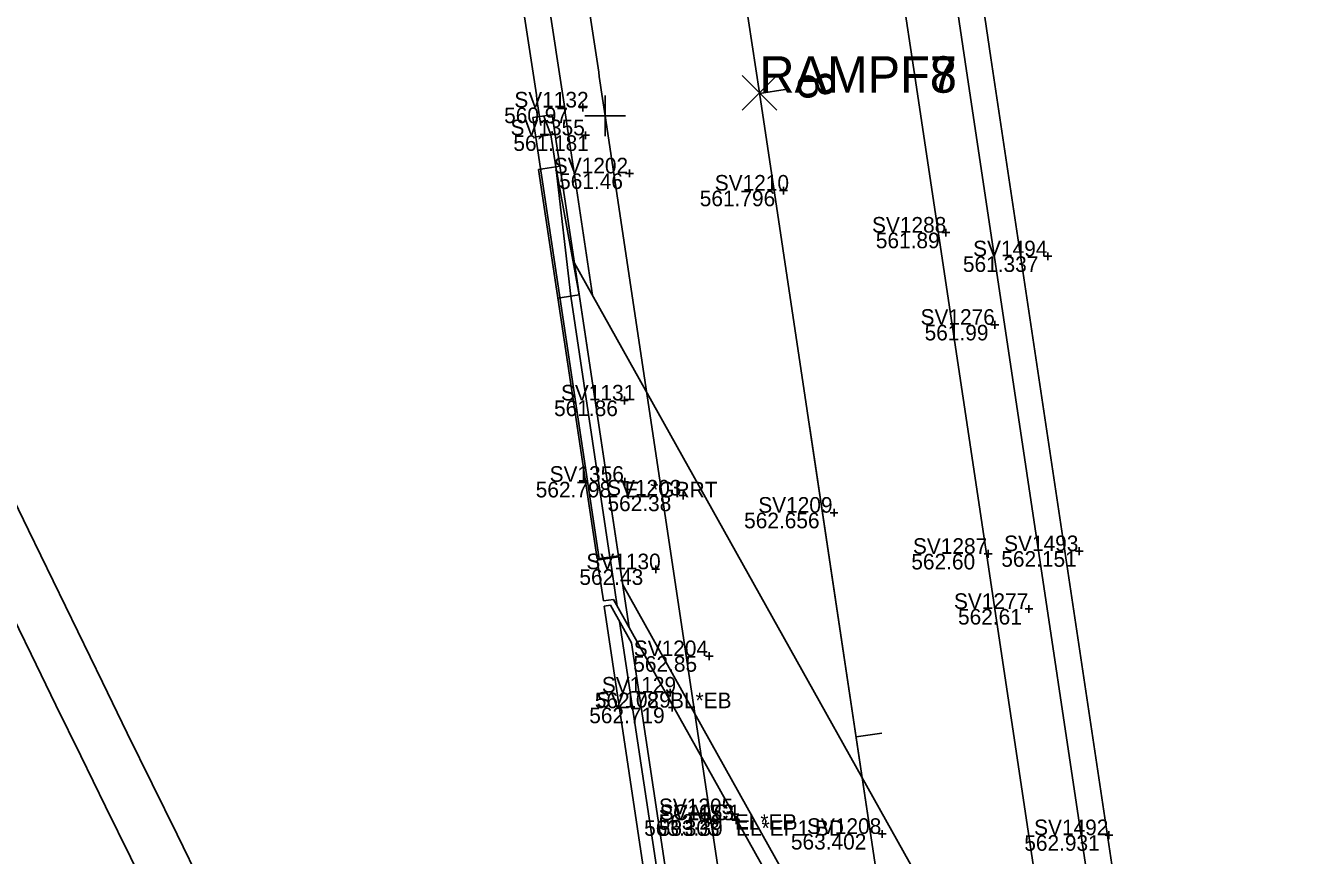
# Model space of a CAD drawing. Extents: x 6334 to 41599, y 9030 to 59113.
# Drawn here: x 21027.9 to 21126.9, y 34551.9 to 34615.6 of the extents above; entities that cross this region are included whole.
import ezdxf

# ---------------------------------------------------------------- set-up
doc = ezdxf.new("R2010")
doc.units = 0
for name, color, linetype in [('BR_P_Rail_Object', 7, 'Continuous'), ('BR_P_Sub_Backwall', 7, 'Continuous'), ('BR_X_Gen_Approach_Slab', 7, 'Continuous'), ('BR_X_Slab_Centerline', 7, 'Continuous'), ('BR_X_SV_Deck_Top', 7, 'Continuous'), ('BR_X_SV_Deck_Top_Text', 7, 'Continuous'), ('GE_P_CL_20', 7, 'Continuous'), ('GE_X_CL_20', 7, 'Continuous'), ('GE_X_CL_50', 7, 'Continuous'), ('GK_Visualization', 7, 'Continuous'), ('PM_X_CL_Double_Solid', 7, 'Continuous'), ('PM_X_Lane_Line', 7, 'Continuous'), ('PV_X_EOP', 7, 'Continuous'), ('PV_X_Shoulder', 7, 'Continuous'), ('RD_X_GR_Lt', 7, 'Continuous'), ('RD_X_GR_Rt', 7, 'Continuous'), ('SV_X_Shot_Marker', 7, 'Continuous'), ('SV_X_Text_Comment', 7, 'Continuous'), ('SV_X_Text_Elevation', 7, 'Continuous'), ('SV_X_Text_Name', 7, 'Continuous')]:
    doc.layers.add(name, color=color, linetype=linetype)

msp = doc.modelspace()

# ---------------------------------------------------------------- linework, layer by layer
at = {"layer": 'BR_P_Rail_Object'}
msp.add_line((21073.051, 34571.516), (21074.266, 34569.344), dxfattribs=at)
at = {"layer": 'BR_P_Sub_Backwall'}
msp.add_line((21118.505, 34490.24), (21073.051, 34571.516), dxfattribs=at)
at = {"layer": 'BR_X_Gen_Approach_Slab'}
for p, q in [((21070.057, 34597.364), (21073.77, 34572.641)), ((21114.297, 34518.26), (21070.057, 34597.364)), ((21118.01, 34493.537), (21073.77, 34572.641))]:
    msp.add_line(p, q, dxfattribs=at)
at = {"layer": 'BR_X_Slab_Centerline'}
msp.add_line((21088.117, 34584.844), (21156.74, 34127.951), dxfattribs=at)
at = {"layer": 'BR_X_SV_Deck_Top'}
for p, q in [((21068.346, 34608.759), (21066.862, 34608.536)), ((21068.346, 34608.759), (21066.862, 34608.536)), ((21071.953, 34574.645), (21066.862, 34608.536)), ((21068.239, 34607.226), (21067.686, 34608.66)), ((21073.436, 34574.868), (21068.346, 34608.759)), ((21068.568, 34607.276), (21067.085, 34607.053)), ((21068.61, 34604.754), (21068.239, 34607.226)), ((21068.94, 34604.803), (21067.292, 34604.556)), ((21071.788, 34574.621), (21067.292, 34604.556)), ((21069.766, 34594.815), (21068.61, 34604.754)), ((21070.425, 34594.914), (21068.61, 34604.754)), ((21070.425, 34594.914), (21068.777, 34594.667)), ((21072.777, 34574.769), (21069.766, 34594.815)), ((21071.788, 34574.621), (21073.436, 34574.868)), ((21071.8, 34574.538), (21073.448, 34574.786)), ((21072.272, 34571.399), (21071.8, 34574.538)), ((21073.344, 34570.992), (21072.789, 34574.687)), ((21074.266, 34569.344), (21073.448, 34574.786)), ((21073.051, 34571.516), (21072.272, 34571.399)), ((21072.828, 34571.061), (21072.333, 34570.987)), ((21072.333, 34570.987), (21124.136, 34226.081)), ((21074.441, 34568.177), (21072.828, 34571.061)), ((21073.519, 34569.825), (21125.209, 34225.674)), ((21074.441, 34568.177), (21126.13, 34224.026))]:
    msp.add_line(p, q, dxfattribs=at)
at = {"layer": 'BR_X_SV_Deck_Top_Text'}
for p, q in [((21077.875, 34563.2), (21077.275, 34563.2)), ((21077.575, 34563.5), (21077.575, 34562.9)), ((21082.476, 34554.849), (21082.476, 34554.249)), ((21082.776, 34554.549), (21082.176, 34554.549))]:
    msp.add_line(p, q, dxfattribs=at)
at = {"layer": 'GE_P_CL_20'}
for p, q in [((21084.28, 34610.389), (21086.258, 34610.687)), ((21091.707, 34560.944), (21093.684, 34561.241))]:
    msp.add_line(p, q, dxfattribs=at)
at = {"layer": 'GE_X_CL_20'}
msp.add_arc((24529.938, 36271.897), 3906.53, 186.216667, 209.216667, dxfattribs=at)
at = {"layer": 'GE_X_CL_50'}
msp.add_arc((32581.775, 39251.958), 12277.667, 194.525, 202.7166667, dxfattribs=at)
at = {"layer": 'GK_Visualization'}
for p, q in [((21051.298, 34829.989), (21084.271, 34610.451)), ((21051.298, 34829.989), (21084.271, 34610.451)), ((21082.938, 34609.116), (21085.604, 34611.786)), ((21082.938, 34611.786), (21085.604, 34609.116)), ((21082.938, 34609.116), (21085.604, 34611.786)), ((21082.938, 34611.786), (21085.604, 34609.116)), ((21072.416, 34610.24), (21072.416, 34607.12)), ((21084.271, 34610.451), (21262.514, 33423.702)), ((21084.271, 34610.451), (21262.514, 33423.702)), ((21073.976, 34608.68), (21070.856, 34608.68))]:
    msp.add_line(p, q, dxfattribs=at)
for centre, radius, start, end in [((32581.775, 39251.958), 12277.667, 194.525, 202.7166667), ((32581.775, 39251.958), 12277.667, 194.525, 202.7166667), ((24529.914, 36271.941), 3906.53, 186.214966, 209.213797), ((24529.914, 36271.941), 3906.53, 186.214966, 209.213797), ((24529.938, 36271.897), 3906.53, 186.216667, 209.216667), ((24529.938, 36271.897), 3906.53, 186.216667, 209.216667)]:
    msp.add_arc(centre, radius, start, end, dxfattribs=at)
msp.add_spline([(21035.844, 34805.209), (21036.519, 34802.592), (21037.187, 34799.973), (21037.847, 34797.352), (21038.5, 34794.729), (21039.146, 34792.105), (21039.786, 34789.479), (21040.418, 34786.852), (21041.044, 34784.222), (21041.663, 34781.591), (21042.276, 34778.959), (21042.882, 34776.325), (21043.482, 34773.69), (21044.075, 34771.053), (21044.663, 34768.415), (21045.244, 34765.776), (21045.819, 34763.135), (21046.389, 34760.493), (21046.953, 34757.85), (21047.511, 34755.205), (21048.063, 34752.56), (21048.61, 34749.913), (21049.152, 34747.265), (21049.688, 34744.616), (21050.22, 34741.966), (21050.746, 34739.315), (21051.267, 34736.663), (21051.783, 34734.01), (21052.295, 34731.356), (21052.802, 34728.702), (21053.304, 34726.046), (21053.802, 34723.389), (21054.295, 34720.732), (21054.785, 34718.074), (21055.27, 34715.415), (21055.751, 34712.756), (21056.228, 34710.095), (21056.701, 34707.435), (21057.17, 34704.773), (21057.636, 34702.111), (21058.098, 34699.448), (21058.557, 34696.784), (21059.012, 34694.12), (21059.464, 34691.456), (21059.913, 34688.79), (21060.359, 34686.125), (21060.802, 34683.459), (21061.242, 34680.792), (21061.679, 34678.125), (21062.114, 34675.457), (21062.546, 34672.789), (21062.976, 34670.121), (21063.403, 34667.452), (21063.828, 34664.783), (21064.251, 34662.114), (21064.672, 34659.444), (21065.091, 34656.774), (21065.508, 34654.104), (21065.923, 34651.433), (21066.337, 34648.762), (21066.749, 34646.091), (21067.16, 34643.42), (21067.569, 34640.748), (21067.977, 34638.077), (21068.384, 34635.405), (21068.79, 34632.733), (21069.196, 34630.061), (21069.6, 34627.388), (21070.003, 34624.716), (21070.406, 34622.043), (21070.809, 34619.371), (21071.211, 34616.698), (21071.613, 34614.026), (21072.014, 34611.353), (21072.416, 34608.68)], degree=3, dxfattribs=at)
at = {"layer": 'PM_X_CL_Double_Solid'}
for p, q in [((21061.445, 34762.427), (21084.271, 34610.451)), ((21084.271, 34610.451), (21262.514, 33423.702))]:
    msp.add_line(p, q, dxfattribs=at)
at = {"layer": 'PM_X_Lane_Line'}
for start in [186.216667, 191.336069]:
    msp.add_arc((24529.938, 36271.897), 3906.53, start, 209.216667, dxfattribs=at)
at = {"layer": 'PV_X_EOP'}
for p, q in [((21063.164, 34831.771), (21096.138, 34612.234)), ((21096.138, 34612.234), (21274.381, 33425.485)), ((21072.403, 34608.678), (21072.404, 34608.669)), ((21072.404, 34608.669), (21250.647, 33421.92))]:
    msp.add_line(p, q, dxfattribs=at)
for centre, radius, start, end in [((24529.938, 36271.897), 3918.53, 191.336069, 209.216667), ((24531.789, 36272.609), 3896.493, 192.870453, 209.21252)]:
    msp.add_arc(centre, radius, start, end, dxfattribs=at)
msp.add_spline([(21035.844, 34805.209), (21036.519, 34802.592), (21037.187, 34799.973), (21037.847, 34797.352), (21038.5, 34794.729), (21039.146, 34792.105), (21039.786, 34789.479), (21040.418, 34786.852), (21041.044, 34784.222), (21041.663, 34781.591), (21042.276, 34778.959), (21042.882, 34776.325), (21043.482, 34773.69), (21044.075, 34771.053), (21044.663, 34768.415), (21045.244, 34765.776), (21045.819, 34763.135), (21046.389, 34760.493), (21046.953, 34757.85), (21047.511, 34755.205), (21048.063, 34752.56), (21048.61, 34749.913), (21049.152, 34747.265), (21049.688, 34744.616), (21050.22, 34741.966), (21050.746, 34739.315), (21051.267, 34736.663), (21051.783, 34734.01), (21052.295, 34731.356), (21052.802, 34728.702), (21053.304, 34726.046), (21053.802, 34723.389), (21054.295, 34720.732), (21054.785, 34718.074), (21055.27, 34715.415), (21055.751, 34712.756), (21056.228, 34710.095), (21056.701, 34707.435), (21057.17, 34704.773), (21057.636, 34702.111), (21058.098, 34699.448), (21058.557, 34696.784), (21059.012, 34694.12), (21059.464, 34691.456), (21059.913, 34688.79), (21060.359, 34686.125), (21060.802, 34683.459), (21061.242, 34680.792), (21061.679, 34678.125), (21062.114, 34675.457), (21062.546, 34672.789), (21062.976, 34670.121), (21063.403, 34667.452), (21063.828, 34664.783), (21064.251, 34662.114), (21064.672, 34659.444), (21065.091, 34656.774), (21065.508, 34654.104), (21065.923, 34651.433), (21066.337, 34648.762), (21066.749, 34646.091), (21067.16, 34643.42), (21067.569, 34640.748), (21067.977, 34638.077), (21068.384, 34635.405), (21068.79, 34632.733), (21069.196, 34630.061), (21069.6, 34627.388), (21070.003, 34624.716), (21070.406, 34622.043), (21070.809, 34619.371), (21071.211, 34616.698), (21071.613, 34614.026), (21072.014, 34611.353), (21072.416, 34608.68)], degree=3, dxfattribs=at)
at = {"layer": 'PV_X_Shoulder'}
for p, q in [((21067.12, 34832.366), (21100.093, 34612.828)), ((21100.093, 34612.828), (21114.297, 34518.26)), ((21069.436, 34608.233), (21069.437, 34608.224)), ((21069.437, 34608.224), (21071.44, 34594.892))]:
    msp.add_line(p, q, dxfattribs=at)
for radius, start in [(3926.53, 191.341411), (3890.53, 192.866306)]:
    msp.add_arc((24529.938, 36271.897), radius, start, 209.216667, dxfattribs=at)
msp.add_spline([(21032.939, 34804.46), (21033.613, 34801.847), (21034.279, 34799.236), (21034.937, 34796.623), (21035.588, 34794.008), (21036.233, 34791.392), (21036.87, 34788.773), (21037.501, 34786.153), (21038.125, 34783.531), (21038.742, 34780.908), (21039.353, 34778.283), (21039.958, 34775.656), (21040.556, 34773.028), (21041.148, 34770.398), (21041.734, 34767.766), (21042.313, 34765.134), (21042.887, 34762.499), (21043.455, 34759.864), (21044.018, 34757.227), (21044.575, 34754.589), (21045.126, 34751.949), (21045.672, 34749.308), (21046.212, 34746.667), (21046.747, 34744.023), (21047.277, 34741.379), (21047.803, 34738.734), (21048.323, 34736.087), (21048.838, 34733.44), (21049.349, 34730.791), (21049.855, 34728.141), (21050.356, 34725.491), (21050.853, 34722.839), (21051.345, 34720.187), (21051.834, 34717.533), (21052.318, 34714.879), (21052.798, 34712.224), (21053.274, 34709.568), (21053.747, 34706.911), (21054.216, 34704.254), (21054.681, 34701.596), (21055.142, 34698.937), (21055.6, 34696.277), (21056.055, 34693.617), (21056.506, 34690.955), (21056.955, 34688.294), (21057.4, 34685.631), (21057.842, 34682.968), (21058.282, 34680.305), (21058.719, 34677.641), (21059.153, 34674.976), (21059.584, 34672.311), (21060.014, 34669.645), (21060.44, 34666.979), (21060.865, 34664.313), (21061.288, 34661.646), (21061.708, 34658.978), (21062.127, 34656.31), (21062.543, 34653.642), (21062.959, 34650.973), (21063.372, 34648.304), (21063.784, 34645.634), (21064.194, 34642.965), (21064.604, 34640.295), (21065.012, 34637.624), (21065.418, 34634.953), (21065.824, 34632.283), (21066.229, 34629.611), (21066.634, 34626.94), (21067.037, 34624.268), (21067.44, 34621.596), (21067.842, 34618.924), (21068.244, 34616.252), (21068.646, 34613.58), (21069.048, 34610.907), (21069.449, 34608.234)], degree=3, dxfattribs=at)
at = {"layer": 'RD_X_GR_Lt'}
for p, q in [((21058.92, 34900.43), (21102.071, 34613.125)), ((21102.071, 34613.125), (21117.462, 34510.655))]:
    msp.add_line(p, q, dxfattribs=at)
at = {"layer": 'RD_X_GR_Rt'}
msp.add_spline([(21031.002, 34803.96), (21031.676, 34801.35), (21032.34, 34798.744), (21032.997, 34796.137), (21033.647, 34793.527), (21034.29, 34790.916), (21034.926, 34788.303), (21035.556, 34785.688), (21036.178, 34783.071), (21036.795, 34780.452), (21037.405, 34777.832), (21038.008, 34775.21), (21038.605, 34772.586), (21039.196, 34769.961), (21039.781, 34767.334), (21040.36, 34764.706), (21040.933, 34762.076), (21041.5, 34759.445), (21042.061, 34756.812), (21042.617, 34754.178), (21043.168, 34751.542), (21043.713, 34748.906), (21044.252, 34746.268), (21044.787, 34743.628), (21045.316, 34740.988), (21045.84, 34738.346), (21046.36, 34735.703), (21046.875, 34733.059), (21047.384, 34730.414), (21047.89, 34727.768), (21048.39, 34725.121), (21048.887, 34722.472), (21049.379, 34719.823), (21049.867, 34717.173), (21050.35, 34714.522), (21050.83, 34711.87), (21051.306, 34709.217), (21051.777, 34706.563), (21052.246, 34703.908), (21052.71, 34701.252), (21053.171, 34698.596), (21053.629, 34695.939), (21054.083, 34693.281), (21054.534, 34690.622), (21054.982, 34687.963), (21055.427, 34685.303), (21055.869, 34682.642), (21056.308, 34679.98), (21056.745, 34677.318), (21057.179, 34674.656), (21057.61, 34671.992), (21058.039, 34669.328), (21058.465, 34666.664), (21058.89, 34663.999), (21059.312, 34661.333), (21059.732, 34658.667), (21060.151, 34656.001), (21060.567, 34653.334), (21060.982, 34650.666), (21061.395, 34647.998), (21061.807, 34645.33), (21062.218, 34642.661), (21062.627, 34639.992), (21063.034, 34637.323), (21063.441, 34634.653), (21063.847, 34631.982), (21064.252, 34629.312), (21064.656, 34626.641), (21065.059, 34623.97), (21065.462, 34621.298), (21065.865, 34618.627), (21066.267, 34615.955), (21066.668, 34613.282), (21067.07, 34610.61), (21067.471, 34607.937)], degree=3, dxfattribs=at)
at = {"layer": 'SV_X_Shot_Marker'}
for p, q in [((21071.001, 34609.315), (21070.401, 34609.315)), ((21070.701, 34609.615), (21070.701, 34609.015)), ((21071.199, 34607.179), (21070.599, 34607.179)), ((21070.899, 34607.479), (21070.899, 34606.879)), ((21074.585, 34604.252), (21073.985, 34604.252)), ((21074.285, 34604.552), (21074.285, 34603.952)), ((21086.129, 34603.229), (21086.129, 34602.629)), ((21086.429, 34602.929), (21085.829, 34602.929)), ((21098.907, 34599.7), (21098.307, 34599.7)), ((21098.607, 34600), (21098.607, 34599.4)), ((21106.748, 34597.879), (21106.148, 34597.879)), ((21106.448, 34598.179), (21106.448, 34597.579)), ((21102.678, 34592.618), (21102.078, 34592.618)), ((21102.378, 34592.918), (21102.378, 34592.318)), ((21074.187, 34586.801), (21073.587, 34586.801)), ((21073.887, 34587.101), (21073.887, 34586.501)), ((21074.214, 34580.553), (21073.614, 34580.553)), ((21073.914, 34580.853), (21073.914, 34580.253)), ((21078.709, 34579.496), (21078.109, 34579.496)), ((21078.409, 34579.796), (21078.409, 34579.196)), ((21090.013, 34578.479), (21090.013, 34577.879)), ((21090.313, 34578.179), (21089.713, 34578.179)), ((21108.867, 34575.522), (21108.867, 34574.922)), ((21102.158, 34575.017), (21101.558, 34575.017)), ((21101.858, 34575.317), (21101.858, 34574.717)), ((21109.167, 34575.222), (21108.567, 34575.222)), ((21076.599, 34573.831), (21075.999, 34573.831)), ((21076.299, 34574.131), (21076.299, 34573.531)), ((21105.293, 34570.782), (21104.693, 34570.782)), ((21104.993, 34571.082), (21104.993, 34570.482)), ((21080.721, 34567.157), (21080.121, 34567.157)), ((21080.421, 34567.457), (21080.421, 34566.857)), ((21077.4, 34564.653), (21077.4, 34564.053)), ((21077.7, 34564.353), (21077.1, 34564.353)), ((21082.683, 34555.01), (21082.083, 34555.01)), ((21082.383, 34555.31), (21082.383, 34554.71)), ((21082.476, 34554.849), (21082.476, 34554.249)), ((21082.776, 34554.549), (21082.176, 34554.549)), ((21093.723, 34553.795), (21093.723, 34553.195)), ((21111.146, 34553.698), (21111.146, 34553.098)), ((21094.023, 34553.495), (21093.423, 34553.495)), ((21111.446, 34553.398), (21110.846, 34553.398))]:
    msp.add_line(p, q, dxfattribs=at)

# ---------------------------------------------------------------- texts
at = {"layer": 'BR_X_SV_Deck_Top_Text'}
for s, p in [('SV1029', (21071.746, 34563.2)), ('562.719', (21071.188, 34562)), ('CALC1', (21077.631, 34554.549)), ('563.303', (21075.409, 34553.349))]:
    msp.add_text(s, height=1.2, dxfattribs=at).set_placement(p)
at = {"layer": 'GE_P_CL_20'}
msp.add_text('8', height=2.8, rotation=278.54167, dxfattribs=at).set_placement((21087.096, 34611.838))
at = {"layer": 'GK_Visualization'}
for s in ['RAMPF8', 'RAMPF7']:
    msp.add_text(s, height=2.8, dxfattribs=at).set_placement((21084.271, 34610.451))
at = {"layer": 'SV_X_Text_Comment'}
for s, p in [('EL*GRRT', (21073.914, 34579.353)), ('BL*EB', (21077.4, 34563.153)), ('EL*EP', (21082.383, 34553.81)), ('EL*EP1 BD', (21082.476, 34553.349))]:
    msp.add_text(s, height=1.2, dxfattribs=at).set_placement(p)
at = {"layer": 'SV_X_Text_Elevation'}
for s, p in [('560.97', (21064.645, 34608.115)), ('561.181', (21065.355, 34605.979)), ('561.46', (21068.872, 34603.052)), ('561.796', (21079.686, 34601.729)), ('561.89', (21093.223, 34598.5)), ('561.337', (21099.92, 34596.679)), ('561.99', (21096.974, 34591.418)), ('561.86', (21068.483, 34585.601)), ('562.798', (21067.074, 34579.353)), ('562.38', (21072.589, 34578.296)), ('562.656', (21083.097, 34576.979)), ('562.60', (21095.953, 34573.817)), ('562.151', (21102.87, 34574.022)), ('562.43', (21070.431, 34572.631)), ('562.61', (21099.543, 34569.582)), ('562.85', (21074.573, 34565.957)), ('562.78', (21071.617, 34563.153)), ('563.29', (21076.525, 34553.81)), ('563.30', (21076.533, 34553.349)), ('563.402', (21086.693, 34552.295)), ('562.931', (21104.638, 34552.198))]:
    msp.add_text(s, height=1.2, dxfattribs=at).set_placement(p)
at = {"layer": 'SV_X_Text_Name'}
for s, p in [('SV1132', (21065.43, 34609.315)), ('SV1355', (21065.136, 34607.179)), ('SV1202', (21068.466, 34604.252)), ('SV1210', (21080.839, 34602.929)), ('SV1288', (21092.93, 34599.7)), ('SV1494', (21100.705, 34597.879)), ('SV1276', (21096.662, 34592.618)), ('SV1131', (21069.015, 34586.801)), ('SV1356', (21068.142, 34580.553)), ('SV1203', (21072.561, 34579.496)), ('SV1209', (21084.184, 34578.179)), ('SV1287', (21096.076, 34575.017)), ('SV1493', (21103.086, 34575.222)), ('SV1130', (21070.971, 34573.831)), ('SV1277', (21099.231, 34570.782)), ('SV1204', (21074.611, 34567.157)), ('SV1129', (21072.157, 34564.353)), ('SV1205', (21076.545, 34555.01)), ('SV1053', (21076.609, 34554.549)), ('SV1208', (21087.931, 34553.495)), ('SV1492', (21105.393, 34553.398))]:
    msp.add_text(s, height=1.2, dxfattribs=at).set_placement(p)

doc.saveas('drawing.dxf')
